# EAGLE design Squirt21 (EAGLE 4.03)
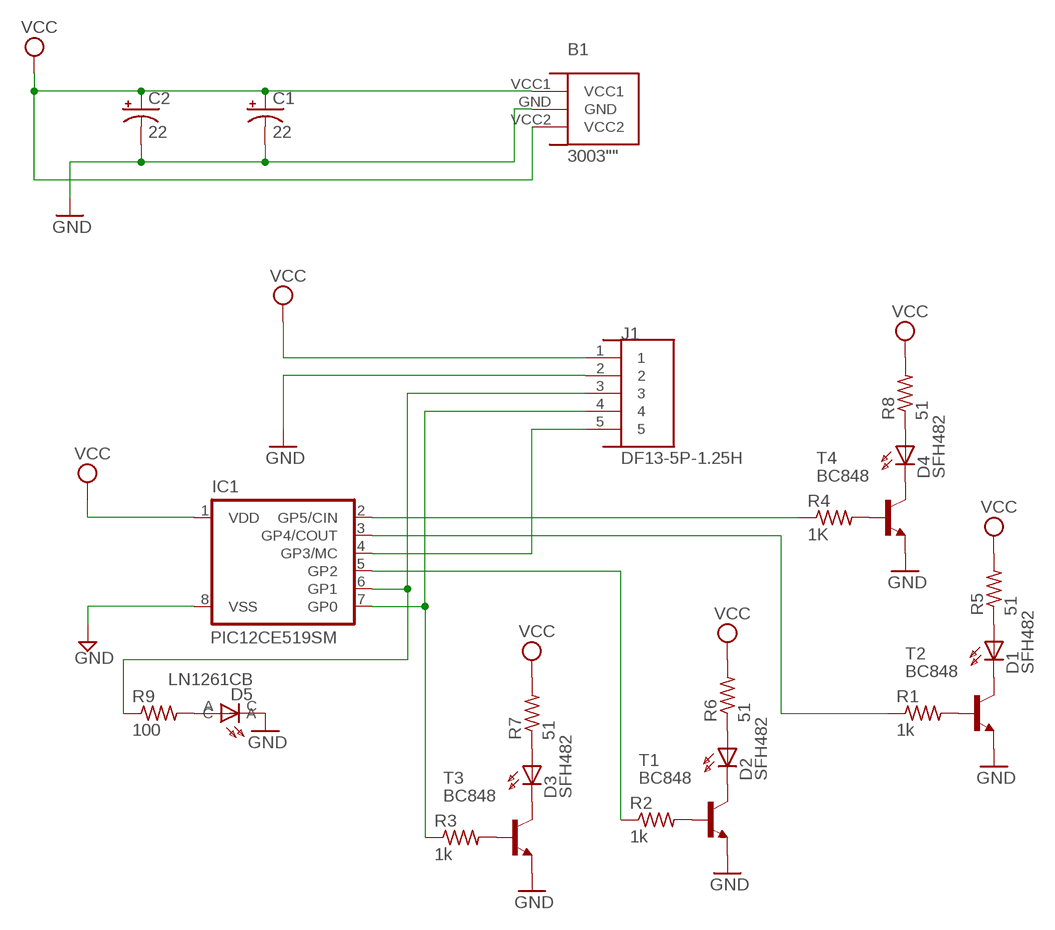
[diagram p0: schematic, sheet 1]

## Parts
B1  3003""  [3003]
C1  22  CPOL-USCT3528  [CT3528]
C2  22  CPOL-USCT3528  [CT3528]
D1  SFH482  [SFH482]
D2  SFH482  [SFH482]
D3  SFH482  [SFH482]
D4  SFH482  [SFH482]
D5  LN1261CB  [LN1_61CB]
IC1  PIC12CE519SM  [SO-08M]
J1  DF13-5P-1.25H  [DF13-5P-1.25H]
R1  1k  R-US_R0805  [R0805]
R2  1k  R-US_R0805  [R0805]
R3  1k  R-US_R0805  [R0805]
R4  1K  R-US_R0805  [R0805]
R5  51  R-US_R0805  [R0805]
R6  51  R-US_R0805  [R0805]
R7  51  R-US_R0805  [R0805]
R8  51  R-US_R0805  [R0805]
R9  100  R-US_R0805  [R0805]
T1  BC848  [SOT23]
T2  BC848  [SOT23]
T3  BC848  [SOT23]
T4  BC848  [SOT23]

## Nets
GND: B1.GND C1.- C2.- D5.C IC1.8(VSS) J1.2 T1.2(E) T2.2(E) T3.2(E) T4.2(E)
GP0: IC1.7(GP0) J1.4 R3.1
GP1: IC1.6(GP1) J1.3 R9.1
GP2: IC1.5(GP2) R2.1
GP3: IC1.4(GP3/MC) J1.5
GP4: IC1.3(GP4/COUT) R1.1
GP5: IC1.2(GP5/CIN) R4.1
N$1: D5.A R9.2
N$3: R4.2 T4.1(B)
N$4: D4.K(C) T4.3(C)
N$5: D4.A R8.1
N$7: R3.2 T3.1(B)
N$8: D3.K(C) T3.3(C)
N$9: D3.A R7.1
N$12: R2.2 T1.1(B)
N$13: D2.K(C) T1.3(C)
N$14: D2.A R6.1
N$17: R1.2 T2.1(B)
N$18: D1.K(C) T2.3(C)
N$19: D1.A R5.1
VCC: B1.VCC1 B1.VCC2 C1.+ C2.+ IC1.1(VDD) J1.1 R5.2 R6.2 R7.2 R8.2

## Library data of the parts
B1 = squirt21:3003: 20mm Coin Cell Holder
C1 C2 = rcl:CPOL-US: POLARIZED CAPACITOR, American symbol
D1-D4 = led:SFH482: IR LED
D5 = squirt21:LN1*61C: Surface Mount Chip LED (GW Type)
IC1 = microchip:PIC12C*?: MICROCONTROLLER
J1 = squirt21:DF13-5P-1.25: DF13 Series: 1.25 mm Pitch Compact Crimp Connector
R1-R9 = rcl:R-US_: RESISTOR, American symbol
T1-T4 = transistor-npn:BC848: NPN TRANSISTOR

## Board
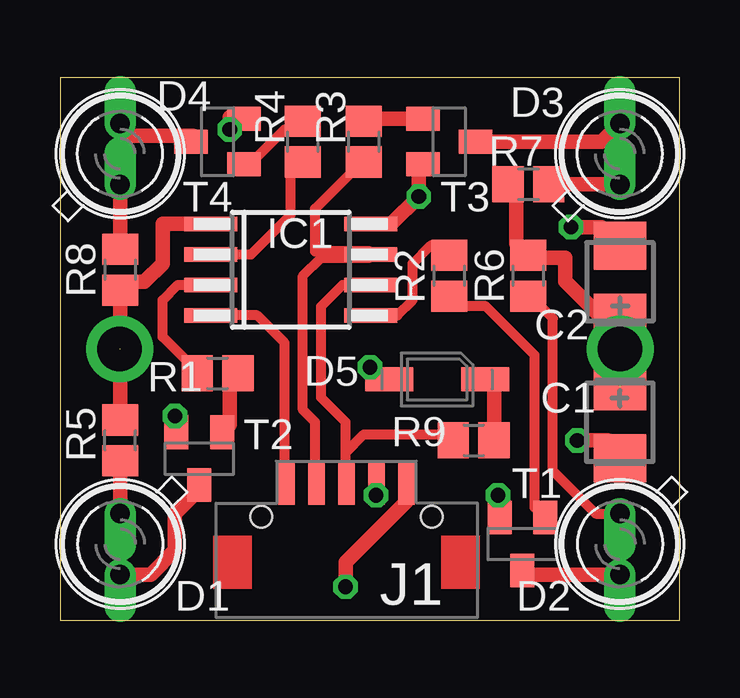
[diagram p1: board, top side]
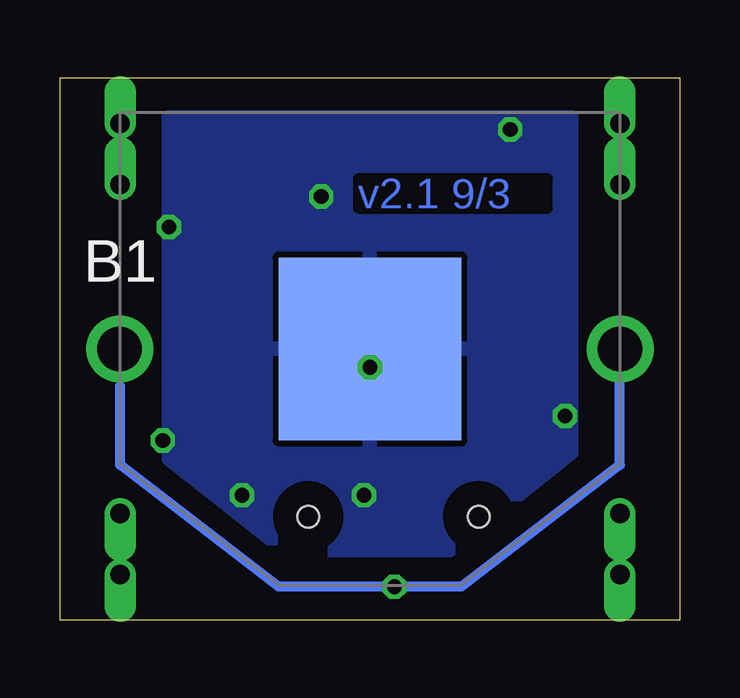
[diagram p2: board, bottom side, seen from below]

Size 25.83 x 22.6 mm. Coordinates in mm from the lower left corner, seen from the top.
Outline: 0,0 25.83,0 25.83,22.6 0,22.6 0,0
Copper layers used: Top, Bottom

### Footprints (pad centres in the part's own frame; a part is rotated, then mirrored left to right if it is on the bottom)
3003 = smd 7.62 x 7.62: GND 0,0 | drill 1.854 round: VCC1 -10.427,0; VCC2 10.427,0
CT3528 = smd 2 x 2.2: + -1.5,0; - 1.5,0
SFH482 = drill 0.813 offset: A -1.27,0; K 1.27,0
LN1_61CB = smd 2 x 1: A 2,0; C -2,0
SO-08M = smd 0.6 x 2.2: 1 -1.905,-3.33; 2 -0.635,-3.33; 3 0.635,-3.33; 4 1.905,-3.33; 5 1.905,3.33; 6 0.635,3.33; 7 -0.635,3.33; 8 -1.905,3.33
DF13-5P-1.25H = smd 0.7 x 1.8: 1 -2.54,-2.54; 2 -1.29,-2.54; 3 -0.04,-2.54; 4 1.21,-2.54; 5 2.46,-2.54 | hole 0.9: -3.59,-1.14; 3.51,-1.14
R0805 = smd 1.3 x 1.5: 1 -0.85,0; 2 0.85,0
SOT23 = smd 1 x 1.4: 1 -0.95,-1.1; 2 0.95,-1.1; 3 0,1.1

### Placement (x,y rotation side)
B1  12.92,11.3 0 bottom
C1  23.33,8.25 270 top
C2  23.33,14.09 90 top
D1  2.5,3.17 270 top
D2  23.33,3.17 270 top
D3  23.33,19.43 90 top
D4  2.5,19.43 90 top
D5  15.71,10.03 0 top
IC1  9.61,14.6 270 top
J1  11.9,3.17 180 top
R1  6.57,10.28 0 top
R2  16.22,14.35 270 top
R3  12.66,19.93 90 top
R4  10.12,19.93 90 top
R5  2.5,7.49 90 top
R6  19.52,14.35 90 top
R7  19.52,18.16 180 top
R8  2.5,14.6 270 top
R9  17.23,7.49 0 top
T1  19.27,3.17 180 top
T2  5.8,6.73 180 top
T3  16.22,19.93 270 top
T4  6.57,19.93 90 top

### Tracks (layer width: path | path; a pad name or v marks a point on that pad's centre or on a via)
GND  (via drill 0.61)
  Top 0.61: T3.2 14.95,18.98 v14.95,17.65 13.8,16.5 IC1.8 | T4.2 7.67,20.95 7.07,20.95 v7.07,20.44 | T2.2 4.85,8.5 v4.79,8.5 | v21.55,7.49 22.82,7.49 22.82,6.73 23.33,6.73 C1.- | D5.C 13.42,10.03 v12.92,10.54 | C2.- 23.33,15.62 22.57,16.38 v21.3,16.38 | T1.2 18.25,4.34 v18.25,5.2 | J1.2 13.17,5.71 v13.17,5.2
  pour Bottom: 9.61,2.92 16.47,2.92 21.3,6.73 21.3,20.95 4.53,20.95 4.53,6.98
GP0
  Top 0.406: 12.41,15.11 12.92,15.11 12.94,15.14 IC1.7 12.92,15.26 12.92,15.36 10.63,15.36 10.63,17.14 12.15,18.66 12.15,19.08 R3.1 | 12.41,15.11 12.15,15.11 | 12.41,15.11 10.88,15.11 10.12,14.35 10.12,8.76 10.63,8.25 10.63,5.77 | J1.4 10.63,5.77 | 10.63,5.77 10.63,5.71
GP1
  Top 0.406: IC1.6 11.77,13.97 10.88,13.08 10.88,9.27 11.9,8.25 11.9,6.22 | R9.1 16.22,7.49 15.96,7.74 12.66,7.74 11.9,6.98 11.9,6.22 | J1.3 11.9,5.71 11.9,6.22
GP2
  Top 0.406: 16.22,15.11 R2.1 16.22,15.62 15.46,15.62 14.69,14.85 14.69,13.33 14.06,12.7 IC1.5
GP3
  Top 0.406: J1.5 9.36,5.71 9.36,11.55 8.22,12.7 IC1.4
GP4
  Top 0.406: IC1.3 4.92,13.97 4.28,13.33 4.28,11.81 5.8,10.28 R1.1
GP5
  Top 0.406: IC1.2 7.96,15.24 9.61,16.89 9.61,18.92 10.12,18.92
  Top 0.61: 10.12,18.92 R4.1
N$1
  Top 0.61: R9.2 18.08,10.03 D5.A
N$3
  Top 0.406: T4.1 7.9,18.98 9.36,20.44 10.12,20.44 R4.2
N$4
  Top 0.61: 5.47,20.19 5.55,20.19 | 5.47,20.19 T4.3 | D4.K 3.01,20.19 5.47,20.19
N$5
  Top 0.61: R8.1 D4.A
N$7
  Top 0.61: 12.66,20.7 R3.2 12.66,20.88 T3.1
N$8
  Top 0.61: T3.3 22.57,19.93 D3.K
N$9
  Top 0.61: R7.1 D3.A
N$12
  Top 0.406: R2.2 16.22,13.33 15.96,13.33 15.71,13.08 17.74,13.08 19.77,11.04 19.77,4.69 20.22,4.25 | 20.22,4.25 20.28,4.19 | T1.1 20.22,4.25
N$13
  Top 0.61: T1.3 19.27,1.9 D2.K
N$14
  Top 0.406: R6.1 19.52,13.58 20.54,12.57 20.54,6.22 22.31,4.44 D2.A
N$17
  Top 0.61: R1.2 7.16,10.03 7.07,10.03 7.07,8.15 T2.1
N$18
  Top 0.61: D1.K 3.77,1.9 4.79,2.92 4.79,4.44 5.8,5.46 T2.3 5.8,5.71
N$19
  Top 0.61: D1.A R5.1
VCC  (via drill 0.61)  (2 unrouted)
  Top 0.61: 2.5,11.3 R8.2 2.5,14.09 3.52,14.09 4.28,14.85 4.28,16.5 IC1.1 | 2.5,8.25 R5.2 2.5,11.3 | 2.5,11.3 B1.VCC2 | 23.33,11.3 B1.VCC1 23.34,9.79 23.33,9.77 | 23.33,9.77 23.33,11.3 | C1.+ 23.33,9.77 | R7.2 18.92,17.9 19.01,17.9 19.01,15.7 R6.2 19.77,15.2 19.77,15.11 21.04,15.11 21.04,14.12 22.59,12.57 23.33,12.57 | J1.1 14.44,4.95 11.9,2.41 v11.9,1.39 | 23.33,12.57 C2.+ | 23.33,11.3 23.33,12.57
  Bottom 0.406: 2.5,11.3 2.5,6.47 9.11,1.39 v11.9,1.39 16.73,1.39 23.33,6.47 C1.+

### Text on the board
Bottom: v2.1 9/3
